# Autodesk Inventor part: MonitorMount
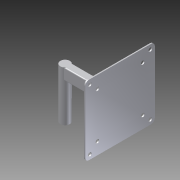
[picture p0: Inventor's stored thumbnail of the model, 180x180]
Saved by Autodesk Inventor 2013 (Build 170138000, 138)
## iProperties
Created: 2004-11
Document SubType Name: Modeling
Designer: Autodesk, Inc.
Manufacturer: Standard
Standards Organization: Custom
Description: SWING ARM MONITOR MOUNT
Mass: 79.9144 g
Surface Area: 366.222 cm^2
Volume: 79.9144 cm^3
Density: 1 g/cm^3
Material: Allgemein
CAGE: 1LJX3
Dept. ID: Product Design
Description #2: ---
Finish #1: ---
Finish #2: ---
Material ID: ---
Project Number: ---
Author: Autodesk, Inc.
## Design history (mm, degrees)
revolve "Revolution1" stored, may be unused: angle "d2" = 90 deg
sketch "Sketch2"
  geometry: L1 (-7.937, 41.275)-(7.938, 41.275) reference; L2 (7.938, 41.275)-(7.938, -41.275) reference; L3 (0, -58.42)-(0, 61.595) reference; L4 (0, 41.275)-(38.1, 41.275); L5 (38.1, 41.275)-(38.1, 22.225); L6 (38.1, 22.225)-(0, 22.225); L7 (0, 22.225)-(0, 41.275); L8 (38.1, 41.275)-(88.9, 44.45); L9 (88.9, 44.45)-(88.9, 19.05); L10 (88.9, 19.05)-(38.1, 22.225); L11 (88.9, 31.75)-(38.1, 31.75)
  constraints: 16 end point, 3 midpoint, 3 parallel, 2 perpendicular, 1 horizontal, 1 point on line, 1 other
  dimensions: "d3" = 19.05 distance between parallel lines of L4 L6; "d4" = 38.1 distance between parallel lines of L3 L5; "d5" = 25.4 distance of L8.end L9.end; "d6" = 88.9 distance between parallel lines of L3 L9
extrude "Extrusion1" join sketch "Sketch2" stored distance "d7" = 12.7; taper "d8" = 0 deg
sketch "Sketch4"
  geometry: L1 (0, 25.4)-(0, 0) reference; L2 (12.7, 0)-(0, 0) reference; L3 (12.7, 0)-(12.7, 25.4) reference; L4 (12.7, 25.4)-(0, 25.4) reference; L5 (-44.831, 70.231)-(57.531, 70.231); L6 (63.881, 63.881)-(63.881, -38.481); L7 (57.531, -44.831)-(-44.831, -44.831); L8 (-51.181, -38.481)-(-51.181, 63.881); A1 r 6.35 centre (-44.831, 63.881) between (-44.831, 70.231) and (-51.181, 63.881); A2 r 6.35 centre (57.531, 63.881) between (63.881, 63.881) and (57.531, 70.231); A3 r 6.35 centre (57.531, -38.481) between (57.531, -44.831) and (63.881, -38.481); A4 r 6.35 centre (-44.831, -38.481) between (-51.181, -38.481) and (-44.831, -44.831); 6 further points
  constraints: 8 end point, 8 point on circle, 8 tangent, 4 centre point, 4 midpoint, 4 point on line, 3 equal radius, 2 parallel, 2 perpendicular, 1 horizontal, 1 horizontal alignment, 1 vertical alignment
  dimensions: "d9" = 115.062 distance of point (-51.181, 70.231) point (63.881, 70.231); "d10" = 6.35 radius of A1
extrude "Extrusion2" join sketch "Sketch4" distance "d11" = 1.905; taper "d12" = 0 deg
sketch "Sketch5"
  geometry: L1 (-57.531, 70.231)-(44.831, 70.231) reference; L2 (-63.881, -38.481)-(-63.881, 63.881) reference; L3 (44.831, -44.831)-(-57.531, -44.831) reference; L4 (51.181, 63.881)-(51.181, -38.481) reference; L5 (-12.7, 0)-(-12.7, 25.4) reference; L6 (-12.7, 25.4)-(0, 25.4) reference; L7 (0, 25.4)-(0, 0) reference; L8 (-12.7, 0)-(0, 0) reference; L9 (-23.813, 44.45)-(11.113, 44.45); L10 (17.463, 38.1)-(17.463, -12.7); L11 (11.113, -19.05)-(-23.813, -19.05); L12 (-30.163, -12.7)-(-30.163, 38.1); L13 (-12.7, 25.4)-(0, 25.4) reference; L14 (-12.7, 0)-(-12.7, 25.4) reference; A1 r 6.35 centre (44.831, 63.881) between (51.181, 63.881) and (44.831, 70.231) reference; A2 r 6.35 centre (-57.531, 63.881) between (-57.531, 70.231) and (-63.881, 63.881) reference; A3 r 6.35 centre (-57.531, -38.481) between (-63.881, -38.481) and (-57.531, -44.831) reference; A4 r 6.35 centre (44.831, -38.481) between (44.831, -44.831) and (51.181, -38.481) reference; A5 r 6.35 centre (-23.813, 38.1) between (-23.813, 44.45) and (-30.163, 38.1); A6 r 6.35 centre (11.113, 38.1) between (17.463, 38.1) and (11.113, 44.45); A7 r 6.35 centre (11.113, -12.7) between (11.113, -19.05) and (17.463, -12.7); A8 r 6.35 centre (-23.813, -12.7) between (-30.163, -12.7) and (-23.813, -19.05); 4 further points
  constraints: 8 end point, 8 point on circle, 8 tangent, 4 centre point, 4 midpoint, 3 equal radius, 2 parallel, 1 horizontal, 1 horizontal alignment, 1 perpendicular, 1 vertical alignment
  dimensions: "d13" = 6.35 radius of A5; "d14" = 63.5 distance between parallel lines of L11 L9; "d15" = 47.625 distance between parallel lines of L10 L12
extrude "Extrusion3" join sketch "Sketch5" distance "d17" = 6.35; taper "d18" = 0 deg
fillet "Fillet1" dims "d19" = 3.175
fillet "Fillet2" dims "d20" = 1.5875
sketch "Sketch6"
  geometry: L1 (-44.831, 70.231)-(57.531, 70.231) reference; L2 (-51.181, -38.481)-(-51.181, 63.881) reference; L3 (57.531, -44.831)-(-44.831, -44.831) reference; L4 (63.881, 63.881)-(63.881, -38.481) reference; L5 (6.35, 70.231)-(6.35, -44.831); L6 (-51.181, 12.7)-(63.881, 12.7); L7 (6.35, 12.7)-(-44.831, -38.481); C1 r 3 at (-43.65, -37.3); C2 r 3 at (-31.15, -24.8); A1 r 6.35 centre (-44.831, 63.881) between (-44.831, 70.231) and (-51.181, 63.881) reference; A2 r 6.35 centre (-44.831, -38.481) between (-51.181, -38.481) and (-44.831, -44.831) reference; A3 r 6.35 centre (57.531, -38.481) between (57.531, -44.831) and (63.881, -38.481) reference; A4 r 6.35 centre (57.531, 63.881) between (63.881, 63.881) and (57.531, 70.231) reference
  constraints: 6 end point, 5 midpoint, 2 centre point, 2 point on line, 1 equal radius
  dimensions: "d21" = 75 diameter of C2.centre L5; "d22" = 100 diameter of C1.centre L5; "d23" = 6 diameter of C2
extrude "Extrusion4" cut sketch "Sketch6" stored distance "d24" = 6.35; taper "d25" = 0 deg
workplane "Work Plane1"
mirror "Mirror1"
mirror "Mirror2"
body "Solid1"
sketch "Sketch1"
  geometry: L1 (0, 41.275)-(7.938, 41.275); L2 (7.938, 41.275)-(7.938, -41.275); L3 (7.938, -41.275)-(0, -41.275); L4 (0, -41.275)-(0, 41.275); 2 further points
  constraints: 8 end point, 2 midpoint, 2 parallel, 1 coincident, 1 horizontal, 1 perpendicular
  dimensions: "d0" = 15.875 diameter of L2 L4; "d1" = 82.55 distance between parallel lines of L3 L1
node "Projected Loop1"
node "Projected Loop2"
node "Projected Loop3"
other parameters: "d16" = 6.35
